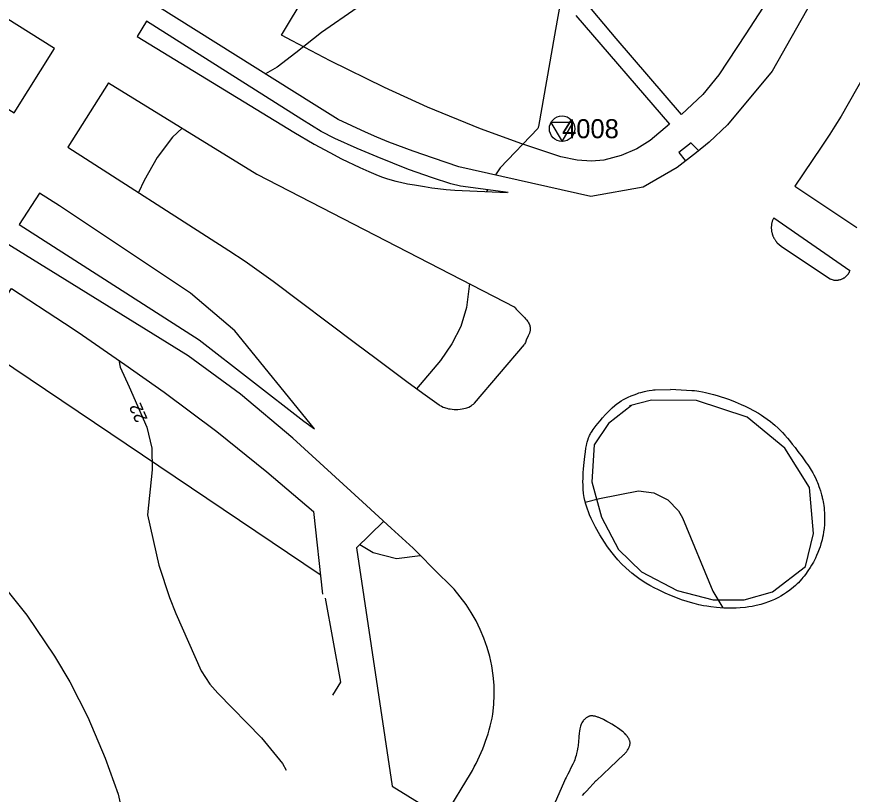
# Model space of a CAD drawing. Extents: x 67169 to 69652, y 20189 to 22818.
# Drawn here: x 69362.6 to 69428.4, y 21145.5 to 21206.6 of the extents above; entities that cross this region are included whole.
import ezdxf

# ---------------------------------------------------------------- set-up
doc = ezdxf.new("R2010")
doc.units = 0
for name, color, linetype in [('HOJDKURVOR_2014', 7, 'Continuous'), ('HOJDKURVOR_TEXTER_2014', 7, 'Continuous'), ('MUR_STAKET', 7, 'Continuous'), ('MUR_STAKET_SYMBOL', 7, 'Continuous'), ('STOMPUNKTER', 7, 'Continuous'), ('STOMPUNKTER TEXT', 7, 'Continuous'), ('VAGAR 121', 7, 'Continuous'), ('VAGAR 123', 7, 'Continuous')]:
    doc.layers.add(name, color=color, linetype=linetype)

msp = doc.modelspace()

# ---------------------------------------------------------------- linework, layer by layer
at = {"layer": 'HOJDKURVOR_2014'}
msp.add_line((69399.657, 21193.042), (69399.595, 21192.9), dxfattribs=at)
for points in [[(69401.004, 21221.966), (69399.416, 21220.265), (69397.818, 21217.756), (69396.759, 21214.975), (69395.715, 21211.11), (69395.602, 21210.93), (69391.846, 21208.859), (69389.418, 21207.353), (69386.622, 21205.406), (69384.593, 21203.795), (69383.131, 21202.674), (69382.213, 21202.14)], [(69405.482, 21208.267), (69405.15, 21206.386), (69404.941, 21205.2), (69403.676, 21198.005), (69403.664, 21197.952), (69403.649, 21197.9), (69403.628, 21197.85), (69400.658, 21194.747), (69400.296, 21194.211)], [(69375.653, 21197.886), (69374.881, 21197.178), (69373.678, 21195.561), (69372.663, 21193.774), (69372.233, 21192.812)], [(69398.239, 21185.652), (69398.018, 21183.779), (69397.578, 21182.289), (69396.863, 21180.909), (69395.965, 21179.603), (69394.094, 21177.378)], [(69370.663, 21179.628), (69370.789, 21179.085), (69371.48, 21177.531), (69372.87, 21174.359), (69373.28, 21172.71), (69373.301, 21171.011), (69372.939, 21167.465), (69373.822, 21163.518), (69374.647, 21160.962), (69375.15, 21159.713), (69377.142, 21155.196), (69377.837, 21154.15), (69378.249, 21153.672), (69378.466, 21153.442), (69381.904, 21149.92), (69383.545, 21147.897), (69383.827, 21147.379)], [(69370.663, 21179.628), (69370.789, 21179.085), (69371.48, 21177.531), (69372.87, 21174.359), (69373.28, 21172.71), (69373.301, 21171.011)], [(69351.137, 21176.42), (69352.173, 21175.723), (69353.027, 21174.885), (69354.031, 21173.563), (69354.447, 21172.837), (69357.678, 21166.393), (69357.906, 21166.066), (69360.992, 21162.6), (69363.449, 21159.576), (69365.624, 21156.343), (69366.808, 21154.328), (69368.227, 21151.54), (69369.606, 21148.321), (69370.608, 21145.495), (69371.019, 21143.745), (69372.337, 21136.549)], [(69373.301, 21171.011), (69372.939, 21167.465), (69373.822, 21163.518), (69374.647, 21160.962), (69375.15, 21159.713), (69377.142, 21155.196), (69377.837, 21154.15), (69378.249, 21153.672), (69378.466, 21153.442), (69381.904, 21149.92), (69383.545, 21147.897), (69383.827, 21147.379)], [(69407.358, 21168.476), (69408.484, 21168.746), (69411.536, 21169.356), (69412.747, 21169.209), (69413.861, 21168.653), (69414.689, 21167.769), (69414.991, 21167.223), (69417.393, 21161.459), (69418.181, 21160.143)], [(69389.614, 21165.124), (69390.684, 21164.509), (69392.5, 21164.024), (69394.36, 21164.281)]]:
    msp.add_lwpolyline(points, dxfattribs=at)
at = {"layer": 'MUR_STAKET'}
msp.add_line((69354.645, 21184.235), (69386.513, 21162.778), dxfattribs=at)
at = {"layer": 'MUR_STAKET_SYMBOL'}
for p, q in [((69364.266, 21177.757), (69364.266, 21177.757)), ((69378.682, 21168.05), (69378.682, 21168.05))]:
    msp.add_line(p, q, dxfattribs=at)
at = {"layer": 'STOMPUNKTER'}
msp.add_lwpolyline([(69405.533, 21196.837), (69406.411, 21198.317), (69404.658, 21198.317)], close=True, dxfattribs=at)
msp.add_circle((69405.533, 21197.837), 1, dxfattribs=at)
at = {"layer": 'VAGAR 121'}
for p, q in [((69376.138, 21179.979), (69264.593, 21248.762)), ((69372.858, 21206.286), (69372.124, 21205.098)), ((69369.863, 21201.453), (69366.663, 21196.379)), ((69415.671, 21196.735), (69416.267, 21196.116)), ((69422.178, 21190.837), (69428.172, 21186.695)), ((69422.766, 21188.601), (69426.632, 21186)), ((69386.071, 21174.229), (69379.805, 21181.947)), ((69385.985, 21167.733), (69386.678, 21161.235)), ((69393.812, 21164.835), (69395.938, 21162.686)), ((69392.699, 21137.902), (69398.326, 21147.084))]:
    msp.add_line(p, q, dxfattribs=at)
for points in [[(69414.588, 21194.783), (69411.905, 21193.251), (69407.788, 21192.494), (69397.41, 21194.848), (69395.417, 21195.526), (69393.831, 21196.082), (69391.918, 21196.785), (69390.97, 21197.161), (69390.071, 21197.553), (69387.928, 21198.566), (69386.032, 21199.748), (69373.666, 21207.495), (69365.496, 21212.309), (69349.694, 21222.267), (69330.773, 21234.25), (69319.82, 21241.201), (69318.929, 21241.754), (69315.325, 21244.041), (69313.082, 21245.432)], [(69383.474, 21205.2), (69398.827, 21230.748), (69399.112, 21231.224), (69399.716, 21231.67), (69404.422, 21229.163), (69410.865, 21239.593), (69406.636, 21241.752)], [(69431.132, 21222.657), (69430.785, 21221.585), (69430.659, 21220.809), (69430.279, 21219.299), (69429.852, 21217.996), (69429.661, 21217.456), (69427.997, 21213.37), (69427.012, 21211.24), (69426.664, 21210.54), (69422.063, 21202.369), (69418.539, 21198.138), (69417.094, 21196.787), (69416.093, 21195.975), (69414.588, 21194.783)], [(69361.731, 21206.584), (69358.549, 21201.509), (69362.434, 21199.073), (69365.616, 21204.149), (69361.731, 21206.584)], [(69401.284, 21192.826), (69397.534, 21193.323), (69396.791, 21193.492), (69395.335, 21193.971), (69393.455, 21194.627), (69390.981, 21195.618), (69389.419, 21196.284), (69387.652, 21197.079), (69386.582, 21197.608), (69385.057, 21198.569), (69372.858, 21206.286)], [(69372.124, 21205.098), (69384.435, 21197.577), (69386.041, 21196.63), (69387.264, 21195.957), (69388.195, 21195.474), (69389.617, 21194.788), (69390.34, 21194.464), (69391.073, 21194.152), (69391.418, 21194.018), (69391.723, 21193.914), (69391.992, 21193.832), (69392.466, 21193.705), (69392.825, 21193.622), (69393.367, 21193.514), (69393.913, 21193.419), (69394.706, 21193.287), (69395.301, 21193.194), (69395.748, 21193.131), (69396.42, 21193.054), (69396.756, 21193.027), (69397.094, 21193.008), (69401.219, 21192.83)], [(69429.33, 21202.09), (69427.474, 21198.832), (69426.987, 21198.032), (69426.725, 21197.62), (69426.6, 21197.416), (69425.919, 21196.387), (69423.826, 21193.313), (69428.712, 21190.061)], [(69369.863, 21201.453), (69381.521, 21194.271), (69401.817, 21183.808)], [(69415.672, 21196.736), (69414.707, 21195.973), (69415.212, 21195.324)], [(69366.663, 21196.379), (69379.336, 21188.262), (69380.62, 21187.413), (69382.818, 21185.853), (69389.276, 21180.979), (69390.903, 21179.766), (69393.327, 21177.941), (69394.57, 21177.029), (69395.857, 21176.119), (69395.925, 21176.075), (69395.99, 21176.036), (69396.053, 21176.003), (69396.173, 21175.947), (69396.28, 21175.905), (69396.376, 21175.874), (69396.46, 21175.849), (69396.609, 21175.815), (69396.721, 21175.794), (69396.888, 21175.773), (69397.052, 21175.76), (69397.153, 21175.756), (69397.25, 21175.756), (69397.343, 21175.759), (69397.521, 21175.773), (69397.679, 21175.794), (69397.816, 21175.821), (69397.934, 21175.851), (69398.035, 21175.883), (69398.121, 21175.915), (69398.195, 21175.946), (69398.318, 21176.009), (69398.405, 21176.063), (69398.467, 21176.107), (69398.554, 21176.181), (69398.632, 21176.262), (69402.582, 21180.856)], [(69379.805, 21181.947), (69376.299, 21184.909), (69366.013, 21191.767), (69364.432, 21192.779), (69362.835, 21190.298), (69376.986, 21181.229), (69385.222, 21174.829), (69386.071, 21174.229)], [(69422.178, 21190.837), (69422.104, 21190.674), (69422.093, 21190.649), (69422.084, 21190.626), (69422.077, 21190.607), (69422.066, 21190.572), (69422.058, 21190.546), (69422.047, 21190.506), (69422.037, 21190.466), (69422.028, 21190.43), (69422.021, 21190.398), (69422.01, 21190.343), (69422.003, 21190.302), (69421.999, 21190.271), (69421.994, 21190.224), (69421.99, 21190.177), (69421.988, 21190.114), (69421.987, 21190.068), (69421.988, 21190.032), (69421.989, 21189.98), (69421.993, 21189.927), (69421.995, 21189.895), (69421.997, 21189.879), (69421.999, 21189.862), (69422.004, 21189.819), (69422.006, 21189.798), (69422.01, 21189.777), (69422.014, 21189.75), (69422.024, 21189.703), (69422.032, 21189.669), (69422.044, 21189.617), (69422.058, 21189.566), (69422.063, 21189.547), (69422.067, 21189.533), (69422.073, 21189.512), (69422.076, 21189.502), (69422.08, 21189.492), (69422.088, 21189.468), (69422.104, 21189.426), (69422.117, 21189.396), (69422.137, 21189.35), (69422.157, 21189.305), (69422.171, 21189.275), (69422.181, 21189.253), (69422.19, 21189.237), (69422.203, 21189.213), (69422.216, 21189.189), (69422.231, 21189.164), (69422.258, 21189.121), (69422.279, 21189.09), (69422.312, 21189.043), (69422.344, 21188.997), (69422.391, 21188.928), (69422.404, 21188.911), (69422.414, 21188.899), (69422.421, 21188.89), (69422.433, 21188.877), (69422.446, 21188.866), (69422.766, 21188.601)], [(69428.172, 21186.695), (69428.12, 21186.571), (69428.114, 21186.558), (69428.109, 21186.546), (69428.099, 21186.525), (69428.091, 21186.51), (69428.078, 21186.488), (69428.065, 21186.465), (69428.049, 21186.437), (69428.033, 21186.413), (69428.019, 21186.392), (69427.993, 21186.357), (69427.972, 21186.331), (69427.956, 21186.312), (69427.931, 21186.284), (69427.905, 21186.256), (69427.879, 21186.231), (69427.83, 21186.186), (69427.786, 21186.149), (69427.746, 21186.119), (69427.71, 21186.094), (69427.678, 21186.074), (69427.62, 21186.041), (69427.576, 21186.018), (69427.542, 21186.002), (69427.489, 21185.98), (69427.435, 21185.96), (69427.368, 21185.938), (69427.308, 21185.922), (69427.256, 21185.911), (69427.209, 21185.903), (69427.169, 21185.898), (69427.133, 21185.895), (69427.102, 21185.894), (69427.049, 21185.895), (69427.009, 21185.898), (69426.979, 21185.902), (69426.934, 21185.91), (69426.891, 21185.921), (69426.632, 21186)], [(69352.615, 21177.942), (69355.459, 21182.769), (69354.221, 21183.593), (69354.893, 21184.613), (69357.368, 21183.183), (69357.975, 21184.03), (69360.364, 21182.448), (69362.228, 21185.27), (69366.397, 21182.552), (69367.483, 21181.845), (69371.152, 21179.287)], [(69401.747, 21183.841), (69401.83, 21183.742), (69401.913, 21183.649), (69402.59, 21182.967), (69402.667, 21182.88), (69402.73, 21182.804), (69402.83, 21182.668), (69402.895, 21182.564), (69402.936, 21182.485), (69402.986, 21182.363), (69403.004, 21182.302), (69403.018, 21182.239), (69403.028, 21182.159), (69403.028, 21182.083), (69403.021, 21182.01), (69403.01, 21181.941), (69402.995, 21181.875), (69402.957, 21181.75), (69402.916, 21181.64), (69402.875, 21181.542), (69402.718, 21181.197), (69402.644, 21181.025), (69402.611, 21180.94), (69402.582, 21180.856)], [(69393.812, 21164.835), (69392.084, 21166.421), (69389.824, 21168.502), (69384.355, 21173.487), (69380.247, 21176.96), (69376.138, 21179.979)], [(69393.812, 21164.835), (69392.084, 21166.421), (69389.824, 21168.502), (69384.355, 21173.487), (69380.247, 21176.96), (69376.138, 21179.979)], [(69371.152, 21179.287), (69374.236, 21177.12), (69378.383, 21174.02), (69382.314, 21170.855), (69385.985, 21167.733)], [(69414.069, 21177.338), (69415.726, 21177.25), (69415.944, 21177.233), (69416.134, 21177.211), (69416.299, 21177.187), (69416.587, 21177.134), (69416.802, 21177.087), (69417.124, 21177.011), (69417.446, 21176.928), (69417.725, 21176.852), (69417.966, 21176.78), (69418.384, 21176.642), (69418.693, 21176.529), (69419.154, 21176.346), (69419.612, 21176.148), (69419.919, 21176.008), (69420.184, 21175.88), (69420.638, 21175.644), (69420.971, 21175.454), (69421.216, 21175.304), (69421.396, 21175.185), (69421.663, 21174.999), (69421.924, 21174.8), (69422.107, 21174.652), (69422.263, 21174.519), (69422.527, 21174.28), (69422.718, 21174.095), (69422.857, 21173.953), (69423.06, 21173.733), (69423.256, 21173.506), (69423.411, 21173.319), (69423.638, 21173.038), (69423.862, 21172.752), (69424.086, 21172.459), (69424.417, 21172.016), (69424.741, 21171.567), (69424.861, 21171.395), (69424.963, 21171.243), (69425.134, 21170.972), (69425.255, 21170.765), (69425.342, 21170.607), (69425.464, 21170.365), (69425.575, 21170.118), (69425.625, 21169.998), (69425.665, 21169.892), (69425.732, 21169.706), (69425.779, 21169.565), (69425.845, 21169.353), (69425.907, 21169.139), (69425.936, 21169.035), (69425.978, 21168.879), (69425.998, 21168.801), (69426.017, 21168.722), (69426.036, 21168.635), (69426.066, 21168.482), (69426.086, 21168.367), (69426.112, 21168.194), (69426.135, 21168.021), (69426.157, 21167.819), (69426.171, 21167.641), (69426.178, 21167.486), (69426.183, 21167.212), (69426.179, 21167.007), (69426.164, 21166.699), (69426.137, 21166.393), (69426.102, 21166.118), (69426.062, 21165.88), (69426.02, 21165.673), (69425.978, 21165.493), (69425.892, 21165.18), (69425.819, 21164.947), (69425.758, 21164.773), (69425.658, 21164.514), (69425.548, 21164.256), (69425.456, 21164.058), (69425.371, 21163.889), (69425.293, 21163.745), (69425.15, 21163.499), (69425.037, 21163.319), (69424.858, 21163.051), (69424.669, 21162.786), (69424.564, 21162.646), (69424.471, 21162.527), (69424.388, 21162.426), (69424.239, 21162.253), (69424.121, 21162.128), (69424.03, 21162.036), (69423.887, 21161.901), (69423.735, 21161.769), (69423.442, 21161.536), (69423.181, 21161.348), (69422.948, 21161.195), (69422.74, 21161.071), (69422.555, 21160.968), (69422.225, 21160.804), (69421.97, 21160.693), (69421.776, 21160.616), (69421.477, 21160.512), (69421.171, 21160.421), (69420.808, 21160.33), (69420.49, 21160.265), (69420.211, 21160.218), (69419.968, 21160.184), (69419.541, 21160.142), (69419.221, 21160.124), (69418.981, 21160.118), (69418.621, 21160.121), (69418.263, 21160.137), (69417.677, 21160.182), (69417.237, 21160.231), (69416.908, 21160.277), (69416.661, 21160.319), (69416.292, 21160.393), (69415.923, 21160.484), (69415.627, 21160.567), (69415.372, 21160.646), (69414.934, 21160.794), (69414.61, 21160.914), (69414.127, 21161.106), (69413.645, 21161.312), (69413.329, 21161.454), (69413.057, 21161.584), (69412.823, 21161.702), (69412.421, 21161.919), (69412.125, 21162.093), (69411.905, 21162.231), (69411.58, 21162.451), (69411.258, 21162.687), (69411.011, 21162.883), (69410.572, 21163.265), (69410.213, 21163.615), (69409.916, 21163.934), (69409.668, 21164.223), (69409.459, 21164.482), (69409.111, 21164.953), (69408.863, 21165.32), (69408.507, 21165.893), (69408.168, 21166.493), (69407.977, 21166.857), (69407.823, 21167.178), (69407.7, 21167.459), (69407.601, 21167.707), (69407.522, 21167.924), (69407.401, 21168.308), (69407.327, 21168.598), (69407.281, 21168.818), (69407.227, 21169.15), (69407.195, 21169.487), (69407.18, 21169.808), (69407.176, 21170.09), (69407.178, 21170.337), (69407.195, 21170.77), (69407.217, 21171.095), (69407.263, 21171.581), (69407.321, 21172.065), (69407.368, 21172.434), (69407.409, 21172.709), (69407.445, 21172.914), (69407.478, 21173.067), (69407.506, 21173.181), (69407.555, 21173.352), (69407.614, 21173.522), (69407.656, 21173.627), (69407.697, 21173.716), (69407.735, 21173.793), (69407.771, 21173.858), (69407.837, 21173.97), (69407.89, 21174.052), (69407.973, 21174.173), (69408.06, 21174.292), (69408.217, 21174.498), (69408.337, 21174.649), (69408.521, 21174.872), (69408.71, 21175.092), (69408.941, 21175.348), (69409.118, 21175.534), (69409.254, 21175.67), (69409.464, 21175.871), (69409.683, 21176.066), (69409.829, 21176.186), (69409.961, 21176.284), (69410.078, 21176.365), (69410.183, 21176.432), (69410.371, 21176.542), (69410.516, 21176.619), (69410.739, 21176.726), (69410.97, 21176.824), (69411.2, 21176.915), (69411.401, 21176.99), (69411.578, 21177.052), (69411.734, 21177.101), (69412.007, 21177.178), (69412.214, 21177.225), (69412.369, 21177.254), (69412.605, 21177.284), (69412.723, 21177.294), (69412.842, 21177.299), (69414.06, 21177.328)], [(69410.981, 21176.078), (69409.177, 21174.645), (69408.067, 21172.98), (69407.882, 21170.067), (69408.622, 21167.292), (69409.963, 21164.749), (69411.767, 21162.991), (69414.588, 21161.511), (69417.409, 21160.771), (69419.86, 21160.771), (69422.079, 21161.419), (69424.669, 21163.407), (69425.316, 21165.997), (69424.993, 21169.604), (69423.05, 21172.703), (69420.091, 21175.154), (69416.114, 21176.448), (69412.553, 21176.495), (69410.842, 21176.032)], [(69386.913, 21160.909), (69388.101, 21154.301), (69387.465, 21153.275)], [(69408.201, 21146.555), (69409.304, 21147.59), (69410.401, 21148.609), (69410.441, 21148.648), (69410.475, 21148.684), (69410.503, 21148.716), (69410.526, 21148.744), (69410.567, 21148.796), (69410.596, 21148.836), (69410.618, 21148.867), (69410.65, 21148.916), (69410.682, 21148.967), (69410.723, 21149.034), (69410.755, 21149.092), (69410.782, 21149.144), (69410.803, 21149.189), (69410.82, 21149.228), (69410.833, 21149.263), (69410.853, 21149.323), (69410.865, 21149.369), (69410.873, 21149.403), (69410.881, 21149.454), (69410.886, 21149.505), (69410.886, 21149.531), (69410.885, 21149.555), (69410.883, 21149.577), (69410.88, 21149.598), (69410.872, 21149.638), (69410.862, 21149.673), (69410.851, 21149.703), (69410.841, 21149.73), (69410.819, 21149.776), (69410.802, 21149.811), (69410.772, 21149.863), (69410.741, 21149.915), (69410.716, 21149.954), (69410.669, 21150.022), (69410.627, 21150.078), (69410.59, 21150.125), (69410.557, 21150.165), (69410.497, 21150.231), (69410.45, 21150.278), (69410.413, 21150.313), (69410.355, 21150.364), (69410.294, 21150.414), (69410.082, 21150.575), (69409.896, 21150.708), (69409.732, 21150.818), (69409.44, 21151), (69409.216, 21151.128), (69409.045, 21151.221), (69408.779, 21151.357), (69408.503, 21151.489), (69408.433, 21151.521), (69408.371, 21151.546), (69408.317, 21151.565), (69408.27, 21151.581), (69408.187, 21151.605), (69408.125, 21151.62), (69408.079, 21151.63), (69408.009, 21151.642), (69407.939, 21151.651), (69407.904, 21151.654), (69407.872, 21151.655), (69407.842, 21151.654), (69407.813, 21151.653), (69407.76, 21151.646), (69407.713, 21151.637), (69407.673, 21151.626), (69407.637, 21151.614), (69407.606, 21151.602), (69407.579, 21151.59), (69407.532, 21151.566), (69407.496, 21151.545), (69407.47, 21151.528), (69407.43, 21151.5), (69407.39, 21151.469), (69407.336, 21151.421), (69407.29, 21151.376), (69407.249, 21151.334), (69407.214, 21151.293), (69407.183, 21151.255), (69407.132, 21151.182), (69407.092, 21151.117), (69407.062, 21151.059), (69407.038, 21151.008), (69407.001, 21150.916), (69406.977, 21150.846), (69406.948, 21150.737), (69406.923, 21150.625), (69406.893, 21150.446), (69406.875, 21150.288), (69406.853, 21150.01), (69406.825, 21149.595), (69406.802, 21149.389), (69406.787, 21149.287), (69406.767, 21149.185), (69406.711, 21148.904), (69406.667, 21148.693), (69406.631, 21148.536), (69406.599, 21148.419), (69406.573, 21148.332), (69406.529, 21148.204), (69406.477, 21148.078), (69406.381, 21147.868), (69406.233, 21147.558), (69406.081, 21147.25), (69405.989, 21147.072), (69405.85, 21146.806), (69405.783, 21146.672), (69405.72, 21146.536), (69404.91, 21144.697)], [(69407.134, 21145.389), (69407.291, 21145.563), (69407.45, 21145.735), (69408.224, 21146.576)]]:
    msp.add_lwpolyline(points, dxfattribs=at)
for centre, radius, start, end in [((69387.859, 21153.358), 12.34, 352.64129, 49.10293), ((69384.884, 21154.837), 15.517, 330.02488, 348.62969)]:
    msp.add_arc(centre, radius, start, end, dxfattribs=at)
at = {"layer": 'VAGAR 123'}
for points in [[(69421.294, 21207.328), (69419.992, 21205.308), (69417.866, 21202.066), (69416.596, 21200.522), (69414.929, 21198.964), (69409.791, 21204.935), (69407.436, 21207.73)], [(69406.626, 21206.745), (69413.991, 21198.2), (69412.467, 21196.912), (69411.403, 21196.244), (69410.18, 21195.718), (69408.813, 21195.368), (69407.844, 21195.271), (69406.731, 21195.35), (69405.428, 21195.635), (69402.376, 21196.634), (69399.117, 21197.823), (69394.936, 21199.52), (69391.566, 21201.075), (69387.305, 21203.185), (69384.3, 21204.741), (69383.474, 21205.2)], [(69391.494, 21166.95), (69389.364, 21164.878), (69392.161, 21146.113), (69396.212, 21143.635)]]:
    msp.add_lwpolyline(points, dxfattribs=at)

# ---------------------------------------------------------------- texts
at = {"layer": 'HOJDKURVOR_TEXTER_2014'}
msp.add_text('22', height=1, rotation=113.66951, dxfattribs=at).set_placement((69372.957, 21175.008))
at = {"layer": 'STOMPUNKTER TEXT'}
msp.add_text('4008', height=1.5, dxfattribs=at).set_placement((69405.533, 21197.087))

doc.saveas('drawing.dxf')
